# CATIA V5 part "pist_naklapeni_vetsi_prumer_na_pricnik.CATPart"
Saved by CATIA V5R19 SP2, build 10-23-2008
Part number: pist_naklapeni_vetsi_prumer_na_pricnik
Bounding box of the stored display mesh (mm): x -54.985 to 54.985, y -7.629 to 387.371, z -55 to 55
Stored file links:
  C:\Users\Martiin\Desktop\9.semestr\Projekt-diplomka\3D model\pist_naklapeni_vetsi_prumer_na_pricnik.CATPart
  E:\Catia\intel_a\startup\materials\Catalog.CATMaterial
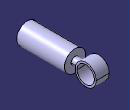
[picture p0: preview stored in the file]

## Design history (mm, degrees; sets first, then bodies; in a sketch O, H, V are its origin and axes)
Body1 (main body)
  Sketch1 on yz-plane, origin (0, 0, 0), H (0, 1, 0), V (0, 0, 1)
    axis line L1 (371.4804, 0) -> (-60.2057, 0)
    point P1 (371.4804, 0)
    point P3 (242.3711, 55)
    line L2 (242.3711, 55) -> (-7.6289, 55)
    line L3 (-7.6289, 55) -> (-7.6289, 50)
    line L4 (-7.6289, 50) -> (235.3711, 50)
    line L5 (235.3711, 50) -> (235.3711, 0)
    point P7 (235.3711, 0)
    line L6 (242.3711, 55) -> (242.3711, 0)
    point P8 (242.3711, 0)
    "Radius" L4 L1 = 50
    "Radius" L1 L2 = 55
    distance L3 P3 = 250
    distance L5 L6 = 7
    coincidence: P1 H, P7 L1, P8 L1
    horizontal: L1 H, L2 H, L4 H
    vertical: L3 V, L5 V, L6 V
  Shaft1: profile Sketch1, axis Sketch1.L1, angle 360
  Sketch2 on yz-plane, origin (0, 0, 0), H (0, 1, 0), V (0, 0, 1)
    circle A1 centre (332.3711, 0) radius 45
    point P1 (332.3711, 0)
    circle A2 centre (332.3711, 0) radius 55
    reference projected line E1 (242.3711, -45) -> (242.3711, 45) from edge [face of Shaft1 from Sketch1.L6 | face of Shaft1 from Sketch1.L2]
    radius A1 = 45
    radius A2 = 55
    distance P1 E1 = 90
    coincidence: P1 H
  Pad1: profile Sketch2, direction (1, 0, 0), length 34, mirrored extent
  Sketch3 on face of Shaft1 from Sketch1.L6, origin (0, 242.3711, 0), H (-1, 0, 0), V (0, 0, 1)
    circle A1 centre (0, 0) radius 20
    radius A1 = 20
  Pad2: profile Sketch3, direction (0, 1, 0), up to the existing solid (limit type 2)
